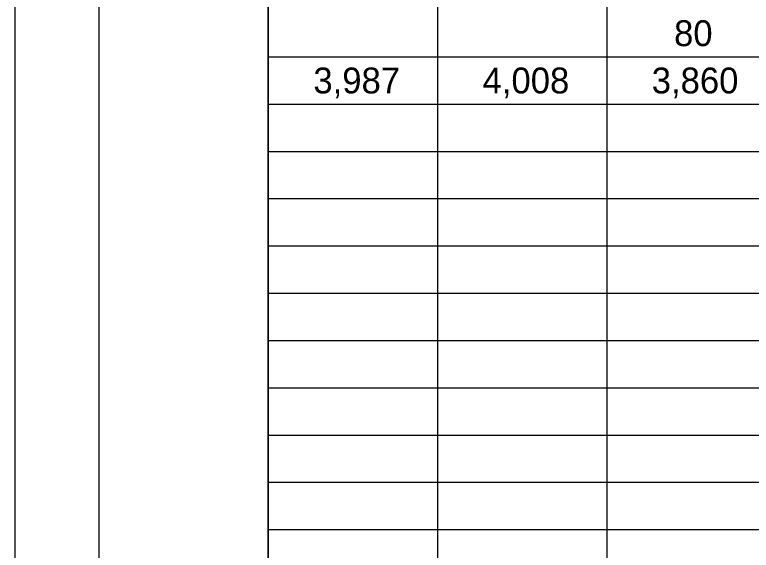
# Model space of a CAD drawing. Extents: x 0 to 34, y 0 to 22.
# Drawn here: x 0 to 4.359, y 15.777 to 18.949 of the extents above; entities that cross this region are included whole.
import ezdxf

# ---------------------------------------------------------------- set-up
doc = ezdxf.new("R2010")
doc.units = 0
for name, color, linetype in [('SH_Border', 7, 'Continuous'), ('SH_Cut_Line', 7, 'Continuous'), ('SH_Text', 7, 'Continuous')]:
    doc.layers.add(name, color=color, linetype=linetype)

msp = doc.modelspace()

# ---------------------------------------------------------------- linework, layer by layer
at = {"layer": 'SH_Border'}
for points in [[(0.5, 21.5), (1.5, 21.5), (1.5, 0.5), (0.5, 0.5)], [(1.5, 21.5), (33.5, 21.5), (33.5, 0.5), (1.5, 0.5)]]:
    msp.add_lwpolyline(points, close=True, dxfattribs=at)
at = {"layer": 'SH_Cut_Line'}
msp.add_lwpolyline([(0, 0), (34, 0), (34, 22), (0, 22)], close=True, dxfattribs=at)
at = {"layer": 'SH_Text'}
for p, q in [((1.5, 20.1), (1.5, 18.7)), ((2.5017, 20.1), (2.5017, 18.7)), ((3.5034, 20.1), (3.5034, 18.7)), ((1.5, 18.7), (6.5084, 18.7)), ((1.5, 18.7), (1.5, 18.14)), ((2.5017, 18.7), (2.5017, 18.14)), ((3.5034, 18.7), (3.5034, 18.14)), ((1.5, 18.42), (6.5084, 18.42)), ((1.5, 18.14), (6.5084, 18.14)), ((1.5, 18.14), (1.5, 17.86)), ((2.5017, 18.14), (2.5017, 17.86)), ((3.5034, 18.14), (3.5034, 17.86)), ((1.5, 17.86), (6.5084, 17.86)), ((1.5, 17.86), (1.5, 17.58)), ((2.5017, 17.86), (2.5017, 17.58)), ((3.5034, 17.86), (3.5034, 17.58)), ((1.5, 17.58), (6.5084, 17.58)), ((1.5, 17.58), (1.5, 17.3)), ((2.5017, 17.58), (2.5017, 17.3)), ((3.5034, 17.58), (3.5034, 17.3)), ((1.5, 17.3), (6.5084, 17.3)), ((1.5, 17.3), (1.5, 17.02)), ((2.5017, 17.3), (2.5017, 17.02)), ((3.5034, 17.3), (3.5034, 17.02)), ((1.5, 17.02), (6.5084, 17.02)), ((1.5, 17.02), (1.5, 16.74)), ((2.5017, 17.02), (2.5017, 16.74)), ((3.5034, 17.02), (3.5034, 16.74)), ((1.5, 16.74), (6.5084, 16.74)), ((1.5, 16.74), (1.5, 16.18)), ((2.5017, 16.74), (2.5017, 16.18)), ((3.5034, 16.74), (3.5034, 16.18)), ((1.5, 16.46), (6.5084, 16.46)), ((1.5, 16.18), (6.5084, 16.18)), ((1.5, 16.18), (1.5, 15.9)), ((2.5017, 16.18), (2.5017, 15.9)), ((3.5034, 16.18), (3.5034, 15.9)), ((1.5, 15.9), (6.5084, 15.9)), ((1.5, 15.9), (1.5, 15.62)), ((2.5017, 15.9), (2.5017, 15.62)), ((3.5034, 15.9), (3.5034, 15.62))]:
    msp.add_line(p, q, dxfattribs=at)

# ---------------------------------------------------------------- texts
for s, p in [('80', (3.9017, 18.7633)), ('3,987', (1.7673, 18.4833)), ('4,008', (2.7685, 18.4833)), ('3,860', (3.7695, 18.4833))]:
    msp.add_text(s, height=0.15333, dxfattribs=at).set_placement(p)

doc.saveas('drawing.dxf')
